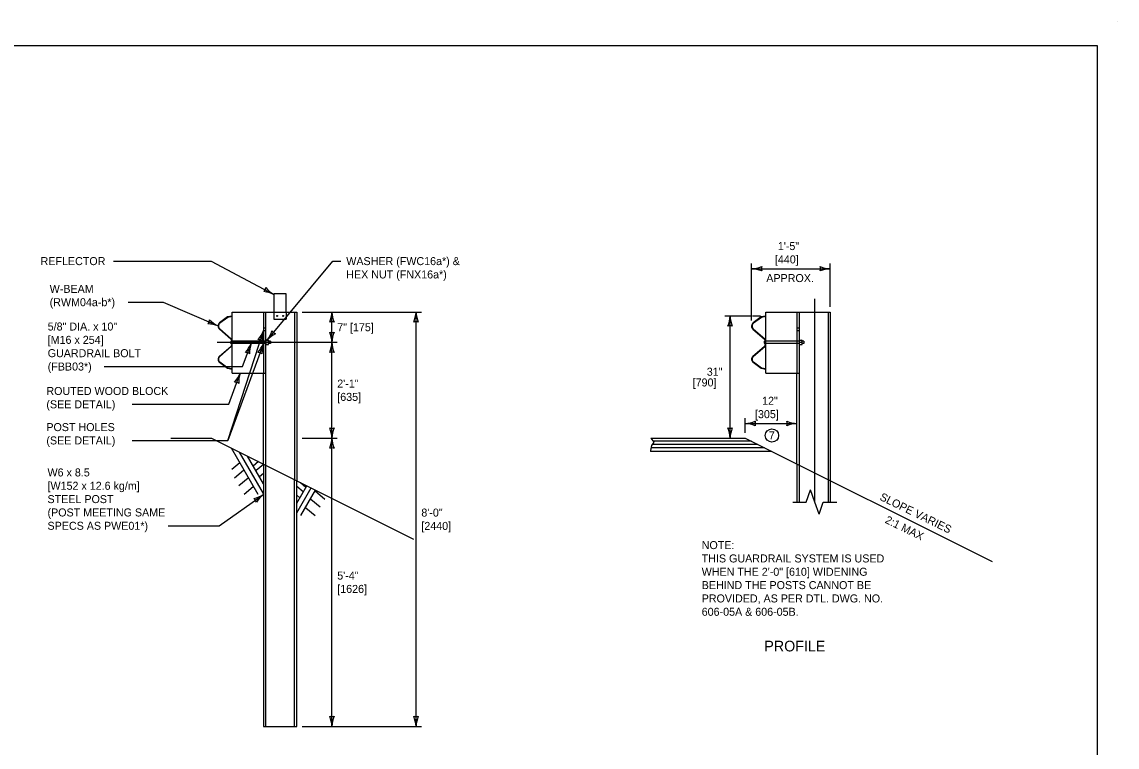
# Model space of a CAD drawing. Extents: x 49991.4 to 50021, y 49987.6 to 50011.4.
# Drawn here: x 50008.69 to 50016.9, y 49993.74 to 49999.18 of the extents above; entities that cross this region are included whole.
import ezdxf

# ---------------------------------------------------------------- set-up
doc = ezdxf.new("R2010")
doc.units = 0
for name, color, linetype in [('Level 1', 7, 'Continuous'), ('Level 2', 7, 'Continuous'), ('Level 3', 7, 'Continuous'), ('Level 4', 7, 'Continuous'), ('Level 5', 7, 'Continuous'), ('Level 6', 7, 'Continuous')]:
    doc.layers.add(name, color=color, linetype=linetype)

msp = doc.modelspace()

# ---------------------------------------------------------------- linework, layer by layer
at = {"layer": 'Level 1'}
for p, q in [((50016.9001, 49999.1756), (50016.9001, 49999.1756)), ((50010.5781, 49997.1367), (50010.5781, 49996.9992)), ((50010.6718, 49997.1367), (50010.5781, 49997.1367)), ((50010.6718, 49996.9992), (50010.6718, 49997.1367)), ((50010.2318, 49996.9635), (50010.1721, 49996.9189)), ((50010.2334, 49996.9599), (50010.1744, 49996.9157)), ((50010.2658, 49996.9696), (50010.2318, 49996.9635)), ((50010.2658, 49996.9655), (50010.2334, 49996.9599)), ((50010.2658, 49996.9992), (50010.5781, 49996.9992)), ((50010.2658, 49996.5402), (50010.2658, 49996.9992)), ((50010.5159, 49996.9992), (50010.5159, 49995.8522)), ((50010.5781, 49996.9992), (50010.5781, 49996.9466)), ((50010.5781, 49996.9992), (50010.6718, 49996.9992)), ((50010.5781, 49996.9466), (50010.6718, 49996.9466)), ((50010.6718, 49996.9992), (50010.7501, 49996.9992)), ((50010.6718, 49996.9992), (50010.6718, 49996.9466)), ((50010.7342, 49996.9992), (50010.7342, 49995.743)), ((50010.7501, 49996.9992), (50010.7501, 49995.7351)), ((50014.2318, 49996.9635), (50014.1721, 49996.9189)), ((50014.2334, 49996.9599), (50014.1744, 49996.9157)), ((50014.2658, 49996.9696), (50014.2318, 49996.9635)), ((50014.2658, 49996.9655), (50014.2334, 49996.9599)), ((50014.2658, 49996.9992), (50014.7501, 49996.9992)), ((50014.2658, 49996.5402), (50014.2658, 49996.9992)), ((50014.5159, 49996.9992), (50014.5159, 49995.8522)), ((50014.7342, 49996.9992), (50014.7342, 49995.743)), ((50014.7501, 49996.9992), (50014.7501, 49995.7351)), ((50010.1704, 49996.871), (50010.2555, 49996.7969)), ((50010.1729, 49996.874), (50010.258, 49996.7999)), ((50014.1704, 49996.871), (50014.2555, 49996.7969)), ((50014.1729, 49996.874), (50014.258, 49996.7999)), ((50010.2639, 49996.7727), (50010.2541, 49996.7727)), ((50010.5159, 49996.7931), (50010.5178, 49996.7931)), ((50010.5178, 49996.7931), (50010.5178, 49996.752)), ((50010.5178, 49996.7727), (50010.5394, 49996.7727)), ((50010.5179, 49996.7892), (50010.5394, 49996.7892)), ((50010.5394, 49996.7562), (50010.5394, 49996.7892)), ((50010.5525, 49996.7823), (50010.5394, 49996.7823)), ((50010.5525, 49996.7823), (50010.5525, 49996.7629)), ((50014.2639, 49996.7727), (50014.2541, 49996.7727)), ((50014.5159, 49996.7931), (50014.5178, 49996.7931)), ((50014.5178, 49996.7931), (50014.5178, 49996.752)), ((50014.5178, 49996.7727), (50014.5394, 49996.7727)), ((50014.5179, 49996.7892), (50014.5394, 49996.7892)), ((50014.5394, 49996.7562), (50014.5394, 49996.7892)), ((50014.5525, 49996.7823), (50014.5394, 49996.7823)), ((50014.5525, 49996.7823), (50014.5525, 49996.7629)), ((50010.1704, 49996.6686), (50010.2552, 49996.7426)), ((50010.1729, 49996.6657), (50010.2594, 49996.7411)), ((50010.5159, 49996.752), (50010.5178, 49996.752)), ((50010.5179, 49996.7562), (50010.5394, 49996.7562)), ((50010.5525, 49996.7629), (50010.5394, 49996.7629)), ((50014.1704, 49996.6686), (50014.2552, 49996.7426)), ((50014.1729, 49996.6657), (50014.2594, 49996.7411)), ((50014.5159, 49996.752), (50014.5178, 49996.752)), ((50014.5179, 49996.7562), (50014.5394, 49996.7562)), ((50014.5525, 49996.7629), (50014.5394, 49996.7629)), ((50010.2318, 49996.5756), (50010.1721, 49996.6208)), ((50010.2334, 49996.5794), (50010.1744, 49996.624)), ((50014.2318, 49996.5756), (50014.1721, 49996.6208)), ((50014.2334, 49996.5794), (50014.1744, 49996.624)), ((50010.2658, 49996.5696), (50010.2318, 49996.5756)), ((50010.2658, 49996.5737), (50010.2334, 49996.5794)), ((50010.2658, 49996.5402), (50010.5159, 49996.5402)), ((50010.5, 49995.8601), (50010.5, 49996.5402)), ((50014.2658, 49996.5696), (50014.2318, 49996.5756)), ((50014.2658, 49996.5737), (50014.2334, 49996.5794)), ((50014.2658, 49996.5402), (50014.5159, 49996.5402)), ((50014.5, 49995.8601), (50014.5, 49996.5402)), ((50009.8071, 49996.0543), (50010.1117, 49996.0543)), ((50010.1117, 49996.0543), (50010.5, 49995.8601)), ((50013.4051, 49996.0543), (50014.1117, 49996.0543)), ((50013.4051, 49996.0543), (50013.4281, 49996.024)), ((50014.1117, 49996.0543), (50015.9637, 49995.1283)), ((50010.4616, 49995.6305), (50010.2601, 49995.9801)), ((50013.4027, 49995.9619), (50013.4015, 49995.9544)), ((50014.3115, 49995.9544), (50013.4015, 49995.9544)), ((50013.4089, 49995.9995), (50013.4027, 49995.9619)), ((50014.2557, 49995.9823), (50013.4061, 49995.9823)), ((50013.4281, 49996.024), (50013.4089, 49995.9995)), ((50014.2077, 49996.0063), (50013.4142, 49996.0063)), ((50014.1598, 49996.0303), (50013.4233, 49996.0303)), ((50010.5, 49995.6383), (50010.32, 49995.9501)), ((50010.5, 49995.712), (50010.3799, 49995.9202)), ((50010.4641, 49995.8781), (50010.4238, 49995.8442)), ((50010.3231, 49995.8686), (50010.2626, 49995.8178)), ((50010.351, 49995.8127), (50010.2824, 49995.7551)), ((50010.5, 49995.8571), (50010.4446, 49995.8105)), ((50010.5, 49995.7889), (50010.4703, 49995.7638)), ((50010.3861, 49995.7545), (50010.3167, 49995.6963)), ((50010.7501, 49995.7351), (50011.6251, 49995.2976)), ((50010.7789, 49995.7207), (50010.8192, 49995.6868)), ((50010.4245, 49995.6892), (50010.3551, 49995.631)), ((50010.7501, 49995.567), (50010.8253, 49995.6975)), ((50010.7501, 49995.6937), (50010.7983, 49995.6531)), ((50010.7501, 49995.4932), (50010.8584, 49995.6809)), ((50010.7501, 49995.6255), (50010.7726, 49995.6064)), ((50010.7814, 49995.4731), (50010.8916, 49995.6643)), ((50010.8882, 49995.6584), (50010.9605, 49995.5977)), ((50010.8569, 49995.5971), (50010.9262, 49995.5389)), ((50010.8185, 49995.5318), (50010.8878, 49995.4736))]:
    msp.add_line(p, q, dxfattribs=at)
msp.add_lwpolyline([(49999.3835, 49998.9992), (50016.7501, 49998.9992), (50016.7501, 49987.7988), (49999.3835, 49987.7988)], close=True, dxfattribs=at)
for centre in [(50010.6024, 49996.9709), (50010.6475, 49996.9709)]:
    msp.add_circle(centre, 0.004, dxfattribs=at)
for centre, radius, start, end in [((50010.1906, 49996.8942), 0.0308, 126.89692, 228.93931), ((50010.1906, 49996.8942), 0.0269, 126.89692, 228.93931), ((50014.1906, 49996.8942), 0.0308, 126.89692, 228.93931), ((50014.1906, 49996.8942), 0.0269, 126.89692, 228.93931), ((50010.2354, 49996.7738), 0.0306, 5.90227, 48.93931), ((50010.2354, 49996.7738), 0.0345, 28.10432, 48.93931), ((50014.2354, 49996.7738), 0.0306, 5.90227, 48.93931), ((50014.2354, 49996.7738), 0.0345, 28.10432, 48.93931), ((50010.2354, 49996.7659), 0.0306, 310.4718, 354.09773), ((50010.2354, 49996.7659), 0.0345, 314.1015, 331.89568), ((50014.2354, 49996.7659), 0.0306, 310.4718, 354.09773), ((50014.2354, 49996.7659), 0.0345, 314.1015, 331.89568), ((50010.1906, 49996.6454), 0.0308, 131.06069, 233.10308), ((50010.1906, 49996.6454), 0.0269, 131.06069, 233.10308), ((50014.1906, 49996.6454), 0.0308, 131.06069, 233.10308), ((50014.1906, 49996.6454), 0.0269, 131.06069, 233.10308)]:
    msp.add_arc(centre, radius, start, end, dxfattribs=at)
for centre, major_axis, ratio, start_param, end_param in [((50010.2638, 49996.7725), (0, 0.0146), 0.663267, 0.091019, 3.253139), ((50010.5309, 49996.781), (0.00829, 0.00104), 0.990733, 4.587776, 7.59993), ((50010.5309, 49996.7644), (-0.00829, -0.00104), 0.990733, 1.547621, 4.582997), ((50014.2638, 49996.7725), (0, 0.0146), 0.663267, 0.091019, 3.253139), ((50014.5309, 49996.781), (0.00829, 0.00104), 0.990733, 4.587776, 7.59993), ((50014.5309, 49996.7644), (-0.00829, -0.00104), 0.990733, 1.547621, 4.582997)]:
    msp.add_ellipse(centre, major_axis=major_axis, ratio=ratio, start_param=start_param, end_param=end_param, dxfattribs=at)
at = {"layer": 'Level 2'}
msp.add_circle((50014.3126, 49996.0741), 0.05, dxfattribs=at)
at = {"layer": 'Level 3'}
for p, q in [((50009.3753, 49997.3818), (50010.1094, 49997.3818)), ((50010.1094, 49997.3818), (50010.5781, 49997.132)), ((50010.5287, 49996.7892), (50011.0217, 49997.3817)), ((50011.0217, 49997.3817), (50011.0814, 49997.3817)), ((50014.1598, 49996.9353), (50014.1598, 49997.3645)), ((50014.7501, 49997.0392), (50014.7501, 49997.3645)), ((50014.1598, 49997.3245), (50014.7501, 49997.3245)), ((50009.4855, 49997.0737), (50009.7475, 49997.0737)), ((50009.7475, 49997.0737), (50010.1598, 49996.8957)), ((50010.7901, 49996.9992), (50011.6841, 49996.9992)), ((50011.0138, 49996.7727), (50011.0138, 49996.9992)), ((50011.6441, 49993.8929), (50011.6441, 49996.9992)), ((50014.1535, 49996.9696), (50013.9586, 49996.9696)), ((50013.9986, 49996.0543), (50013.9986, 49996.9696)), ((50014.2258, 49996.9696), (50014.1663, 49996.9696)), ((50010.2337, 49996.0369), (50010.5, 49996.8601)), ((50011.0138, 49996.0543), (50011.0138, 49996.7727)), ((50010.5, 49996.7629), (50010.2337, 49996.0369)), ((50010.3442, 49996.5913), (50010.4072, 49996.7629)), ((50009.3069, 49996.5913), (50010.3442, 49996.5913)), ((50010.2403, 49996.3079), (50010.3254, 49996.5402)), ((50009.5169, 49996.3079), (50010.2403, 49996.3079)), ((50014.1117, 49996.0943), (50014.1117, 49996.2041)), ((50014.1117, 49996.1641), (50014.5, 49996.1641)), ((50009.5169, 49996.0369), (50010.2337, 49996.0369)), ((50010.7901, 49996.0543), (50011.0538, 49996.0543)), ((50011.0138, 49993.8929), (50011.0138, 49996.0543)), ((50010.169, 49995.397), (50010.5, 49995.6314)), ((50009.7869, 49995.397), (50010.169, 49995.397)), ((50010.7901, 49993.8929), (50011.6841, 49993.8929))]:
    msp.add_line(p, q, dxfattribs=at)
for centre, radius, start, end in [((50014.1483, 49997.5572), 0.233, 272.82731, 292.07716), ((50014.1506, 49997.1024), 0.2223, 67.45601, 87.63952), ((50014.288, 49997.3245), 0.0548, 162.13882, 197.86118), ((50014.7593, 49997.5467), 0.2223, 247.45601, 267.63952), ((50014.6219, 49997.3245), 0.0548, 342.13882, 17.86118), ((50014.7616, 49997.0918), 0.233, 92.82731, 112.07716), ((50010.4649, 49997.1923), 0.0548, 314.08214, 349.8045), ((50010.4788, 49996.9212), 0.233, 64.77063, 84.02048), ((50010.6907, 49997.3237), 0.2223, 219.39933, 239.58284), ((50010.0421, 49996.9465), 0.0548, 318.7908, 354.51316), ((50010.2563, 49997.096), 0.2223, 224.10799, 244.2915), ((50010.7917, 49997.0084), 0.2223, 337.45601, 357.63952), ((50011.2465, 49997.0107), 0.233, 182.82731, 202.07716), ((50011.422, 49997.0083), 0.2223, 337.45601, 357.63952), ((50011.8768, 49997.0107), 0.233, 182.82731, 202.07716), ((50013.7765, 49996.9788), 0.2223, 337.45601, 357.63952), ((50014.2313, 49996.9811), 0.233, 182.82731, 202.07716), ((50010.0782, 49996.6775), 0.233, 69.47929, 88.72914), ((50010.2915, 49996.9372), 0.2223, 319.53322, 339.71672), ((50010.7249, 49996.7994), 0.233, 164.90452, 184.15437), ((50010.3424, 49996.9292), 0.233, 323.06204, 342.31189), ((50010.6107, 49996.8877), 0.0548, 212.37355, 248.09591), ((50011.0138, 49996.871), 0.0548, 72.13882, 107.86118), ((50011.6441, 49996.871), 0.0548, 72.13882, 107.86118), ((50013.9986, 49996.8414), 0.0548, 72.13882, 107.86118), ((50010.4605, 49996.7381), 0.0548, 54.21602, 89.93839), ((50010.6935, 49996.6401), 0.2223, 117.69074, 137.87425), ((50011.0138, 49996.9009), 0.0548, 252.13882, 287.86118), ((50010.7811, 49996.7612), 0.233, 2.82731, 22.07716), ((50010.7917, 49996.7819), 0.2223, 337.45601, 357.63952), ((50011.2359, 49996.7635), 0.2223, 157.45601, 177.63952), ((50011.2465, 49996.7842), 0.233, 182.82731, 202.07716), ((50010.2018, 49996.8478), 0.2223, 317.34855, 337.53206), ((50010.3632, 49996.6425), 0.0548, 52.03136, 87.75372), ((50010.6297, 49996.6937), 0.233, 162.71985, 181.9697), ((50010.2946, 49996.8479), 0.2223, 317.31577, 337.49928), ((50010.4558, 49996.6425), 0.0548, 51.99858, 87.72094), ((50010.7224, 49996.6935), 0.233, 162.68708, 181.93693), ((50011.0138, 49996.6445), 0.0548, 72.13882, 107.86118), ((50010.12, 49996.6252), 0.2223, 317.32342, 337.50693), ((50010.5479, 49996.4709), 0.233, 162.69472, 181.94457), ((50010.2813, 49996.4198), 0.0548, 52.00623, 87.72859), ((50011.0138, 49996.1825), 0.0548, 252.13882, 287.86118), ((50010.7811, 49996.0428), 0.233, 2.82731, 22.07716), ((50011.2359, 49996.0451), 0.2223, 157.45601, 177.63952), ((50013.9986, 49996.1825), 0.0548, 252.13882, 287.86118), ((50013.7659, 49996.0428), 0.233, 2.82731, 22.07716), ((50014.2207, 49996.0451), 0.2223, 157.45601, 177.63952), ((50014.1001, 49996.3968), 0.233, 272.84161, 292.09146), ((50014.1026, 49995.942), 0.2223, 67.47031, 87.65382), ((50014.2399, 49996.1642), 0.0548, 162.15312, 197.87548), ((50014.5092, 49996.3863), 0.2223, 247.45601, 267.63952), ((50014.3718, 49996.1641), 0.0548, 342.13882, 17.86118), ((50014.5115, 49995.9314), 0.233, 92.82731, 112.07716), ((50010.7917, 49996.0634), 0.2223, 337.45601, 357.63952), ((50011.2465, 49996.0658), 0.233, 182.82731, 202.07716), ((50011.0138, 49995.9261), 0.0548, 72.13882, 107.86118), ((50010.3791, 49995.818), 0.2223, 282.76822, 302.95173), ((50010.6439, 49995.4482), 0.233, 128.13952, 147.38937), ((50010.3954, 49995.5573), 0.0548, 17.45103, 53.17339), ((50011.0138, 49994.0211), 0.0548, 252.13882, 287.86118), ((50010.7811, 49993.8814), 0.233, 2.82731, 22.07716), ((50011.2359, 49993.8837), 0.2223, 157.45601, 177.63952), ((50011.6441, 49994.0211), 0.0548, 252.13882, 287.86118), ((50011.4114, 49993.8814), 0.233, 2.82731, 22.07716), ((50011.8662, 49993.8837), 0.2223, 157.45601, 177.63952)]:
    msp.add_arc(centre, radius, start, end, dxfattribs=at)
at = {"layer": 'Level 4'}
for p, q in [((50010.5, 49996.9992), (50010.5, 49996.5402)), ((50014.5, 49996.9992), (50014.5, 49996.5402)), ((50010.5159, 49996.8795), (50010.5, 49996.8795)), ((50010.5159, 49996.8601), (50010.5, 49996.8601)), ((50014.5159, 49996.8795), (50014.5, 49996.8795)), ((50014.5159, 49996.8601), (50014.5, 49996.8601)), ((50010.5159, 49996.7823), (50010.2658, 49996.7823)), ((50014.5159, 49996.7823), (50014.2658, 49996.7823)), ((50010.5159, 49996.7629), (50010.2658, 49996.7629)), ((50014.5159, 49996.7629), (50014.2658, 49996.7629)), ((50010.5, 49995.8601), (50010.5, 49993.8929)), ((50010.5, 49995.8601), (50010.7501, 49995.7351)), ((50010.5159, 49995.8522), (50010.5159, 49993.8929)), ((50014.5, 49995.8601), (50014.5, 49995.575)), ((50014.5159, 49995.8522), (50014.5159, 49995.575)), ((50010.7342, 49993.8929), (50010.7342, 49995.743)), ((50010.7501, 49993.8929), (50010.7501, 49995.7351)), ((50014.7342, 49995.743), (50014.7342, 49995.575)), ((50014.7501, 49995.7351), (50014.7501, 49995.575)), ((50010.5, 49993.8929), (50010.7501, 49993.8929))]:
    msp.add_line(p, q, dxfattribs=at)
at = {"layer": 'Level 5'}
for p, q in [((50014.633, 49995.575), (50014.633, 49997.0992)), ((50010.1541, 49996.7727), (50011.0538, 49996.7727))]:
    msp.add_line(p, q, dxfattribs=at)
at = {"layer": 'Level 6'}
for p, q in [((50014.5682, 49995.575), (50014.6006, 49995.6664)), ((50014.633, 49995.575), (50014.6006, 49995.6664)), ((50014.468, 49995.575), (50014.5682, 49995.575)), ((50014.6654, 49995.4836), (50014.633, 49995.575)), ((50014.6654, 49995.4836), (50014.6978, 49995.575)), ((50014.6978, 49995.575), (50014.7986, 49995.575))]:
    msp.add_line(p, q, dxfattribs=at)

# ---------------------------------------------------------------- texts
at = {"layer": 'Level 2'}
for s, height, p in [('1\'-5"', 0.06, (50014.3566, 49997.4645)), ('WASHER (FWC16a*) &', 0.06, (50011.1214, 49997.3517)), ('[440]', 0.06, (50014.3348, 49997.3645)), ('HEX NUT (FNX16a*)', 0.06, (50011.1214, 49997.2517)), ('APPROX.', 0.06, (50014.2702, 49997.2245)), ('7" [175]', 0.06, (50011.0538, 49996.8559)), ('31"', 0.06, (50013.824, 49996.5222)), ('2\'-1"', 0.06, (50011.0538, 49996.4335)), ('[790]', 0.06, (50013.7182, 49996.4418)), ('[635]', 0.06, (50011.0538, 49996.3335)), ('12"', 0.06, (50014.2386, 49996.3041)), ('[305]', 0.06, (50014.1856, 49996.2041)), ('7', 0.06, (50014.2888, 49996.0441)), ('8\'-0"', 0.06, (50011.6841, 49995.466)), ('[2440]', 0.06, (50011.6841, 49995.366)), ('NOTE:', 0.06, (50013.786, 49995.2221)), ('THIS GUARDRAIL SYSTEM IS USED', 0.06, (50013.786, 49995.1221)), ('5\'-4"', 0.06, (50011.0538, 49994.9936)), ('WHEN THE 2\'-0" [610] WIDENING', 0.06, (50013.786, 49995.0221)), ('BEHIND THE POSTS CANNOT BE', 0.06, (50013.786, 49994.9221)), ('[1626]', 0.06, (50011.0538, 49994.8936)), ('PROVIDED, AS PER DTL. DWG. NO.', 0.06, (50013.786, 49994.8221)), ('606-05A & 606-05B.', 0.06, (50013.786, 49994.7221)), ('PROFILE', 0.08, (50014.2554, 49994.4549))]:
    msp.add_text(s, height=height, dxfattribs=at).set_placement(p)
for s, rotation, p in [('REFLECTOR', 360, (50008.8297, 49997.3518)), ('W-BEAM', 360, (50008.8978, 49997.1437)), ('(RWM04a-b*)', 360, (50008.8978, 49997.0437)), ('5/8" DIA. x 10"', 360, (50008.883, 49996.8613)), ('[M16 x 254]', 360, (50008.883, 49996.7613)), ('GUARDRAIL BOLT', 360, (50008.883, 49996.6613)), ('(FBB03*)', 360, (50008.883, 49996.5613)), ('ROUTED WOOD BLOCK', 360, (50008.8731, 49996.3779)), ('(SEE DETAIL)', 360, (50008.8731, 49996.2779)), ('POST HOLES', 360, (50008.8731, 49996.1069)), ('(SEE DETAIL)', 360, (50008.8731, 49996.0069)), ('W6 x 8.5', 360, (50008.8816, 49995.767)), ('[W152 x 12.6 kg/m]', 360, (50008.8816, 49995.667)), ('STEEL POST', 360, (50008.8816, 49995.567)), ('SLOPE VARIES', 334.00293, (50015.1151, 49995.5936)), ('(POST MEETING SAME', 360, (50008.8816, 49995.467)), ('2:1 MAX', 334.00293, (50015.1547, 49995.4213)), ('SPECS AS PWE01*)', 360, (50008.8816, 49995.367))]:
    msp.add_text(s, height=0.06, rotation=rotation, dxfattribs=at).set_placement(p)

doc.saveas('drawing.dxf')
